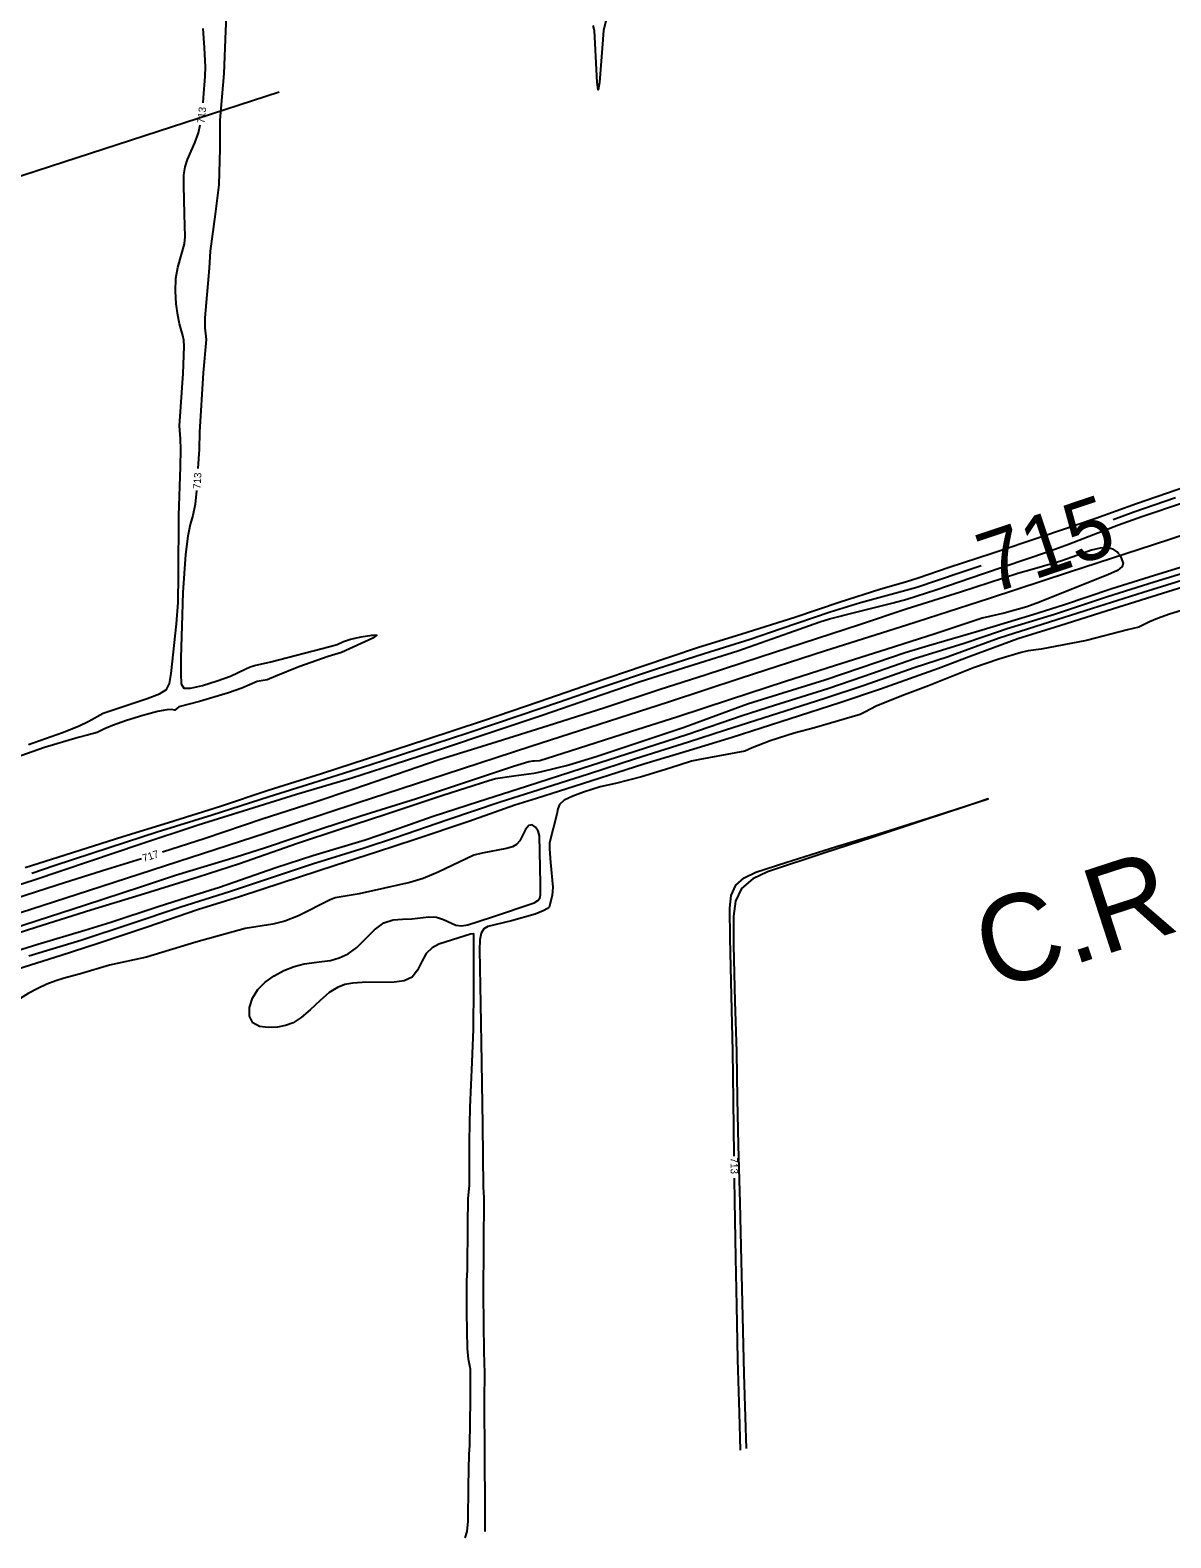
# Model space of a CAD drawing. Extents: x -468548933 to 3387700, y -306089263 to 1207014.
# Drawn here: x 1836234 to 1836853, y 535354 to 536172 of the extents above; entities that cross this region are included whole.
import ezdxf

# ---------------------------------------------------------------- set-up
doc = ezdxf.new("R2010")
doc.units = 0
for name, color, linetype in [('DT_X_Contour_Minor', 7, 'Continuous'), ('Level 14', 7, 'Continuous'), ('Level 19', 7, 'Continuous'), ('Level 40', 7, 'Continuous')]:
    doc.layers.add(name, color=color, linetype=linetype)

msp = doc.modelspace()

# ---------------------------------------------------------------- linework, layer by layer
at = {"layer": 'DT_X_Contour_Minor'}
for points in [[(1836341.23, 536193.74), (1836340.1, 536171.52), (1836339.25, 536148.31), (1836337.09, 536123.13), (1836336.97, 536113.77), (1836337.07, 536107.72), (1836336.39, 536087.89), (1836334.51, 536072.08), (1836331.77, 536051.98), (1836331.22, 536042.83), (1836328.9, 536015.9), (1836328.9, 536010.5), (1836329.58, 536004.08), (1836328.03, 535986.09), (1836325.95, 535953.8), (1836325.72, 535944.58), (1836325.16, 535934.2)], [(1836547.88, 536183.58), (1836545.04, 536171.64), (1836544.29, 536162.04), (1836542.91, 536143.51), (1836542.18, 536139.41), (1836541.6, 536143.49), (1836540.23, 536171.61), (1836539.47, 536174.48)], [(1836327.89, 536132.5), (1836328.18, 536135.23), (1836329.13, 536146.74), (1836329.29, 536152.02), (1836328.72, 536162.23), (1836327.9, 536172.68)], [(1836233.32, 535784.37), (1836251.63, 535790.9), (1836260.31, 535794.36), (1836265.96, 535797.03), (1836273.81, 535801.48), (1836282.37, 535804.33), (1836297.66, 535809.32), (1836304.25, 535811.89), (1836308.04, 535814.24), (1836309.73, 535817.47), (1836310.58, 535823.03), (1836313.55, 535849.89), (1836314.37, 535861.52), (1836314.64, 535876.4), (1836314.76, 535908.67), (1836315.67, 535935.09), (1836315.85, 535944.44), (1836315.69, 535950.3), (1836315.06, 535957.35), (1836317.1, 535985.58), (1836317.74, 536000.21), (1836317.55, 536003.71), (1836317.02, 536006.24), (1836315.19, 536012.55), (1836314.19, 536017.31), (1836313.38, 536023.47), (1836312.97, 536030.39), (1836313.22, 536037.19), (1836314.26, 536043.17), (1836317.82, 536055.94), (1836318.14, 536059.74), (1836317.86, 536072.05), (1836317.41, 536087.59), (1836317.55, 536093.31), (1836318.16, 536097.76), (1836319.4, 536101.75), (1836323.53, 536110.81), (1836325.49, 536116.25), (1836326.42, 536120.59)], [(1836231.46, 535717.64), (1836253.18, 535724.62), (1836284.44, 535734.53), (1836309.13, 535742.21), (1836337.31, 535751.02), (1836363.25, 535759.59), (1836392.07, 535768.74), (1836424.87, 535779.34), (1836448.75, 535787.17), (1836480.08, 535797.54), (1836510.27, 535807.77), (1836538.92, 535817.76), (1836566.58, 535827.14), (1836596.09, 535836.97), (1836620.14, 535844.48), (1836648.76, 535853.54), (1836673.39, 535861.8), (1836694.93, 535868.76), (1836709.42, 535872.89), (1836715.8, 535874.88), (1836732.59, 535880.54), (1836755.76, 535888.24), (1836782.8, 535897.23), (1836812.03, 535907.2), (1836834.12, 535915.13), (1836867.11, 535926.48)], [(1836324.41, 535922.22), (1836323.65, 535914.87), (1836322.37, 535908.67), (1836320.96, 535903.78), (1836319.6, 535897.35), (1836318.45, 535887.51), (1836316.98, 535866.82), (1836316.55, 535854.79), (1836315.92, 535831.41), (1836315.77, 535822.73), (1836315.99, 535817.33), (1836317.44, 535815.01), (1836321.16, 535814.99), (1836327.67, 535816.52), (1836335.51, 535818.91), (1836342.73, 535821.49), (1836351.19, 535825.41), (1836353.54, 535826.57), (1836355.78, 535827.25), (1836364.72, 535829.22), (1836396.69, 535837.58), (1836400.67, 535838.59), (1836404.03, 535840.27), (1836407.86, 535841.51), (1836413.69, 535842.84), (1836419.35, 535843.77), (1836422.07, 535843.67), (1836420, 535842.19), (1836402.92, 535834.38), (1836395.77, 535832.21), (1836379.77, 535826.54), (1836367.39, 535821.57), (1836362.68, 535819.54), (1836357.2, 535818.63), (1836348.88, 535814.94), (1836341.77, 535812.47), (1836326.01, 535807.75), (1836314.83, 535804.95), (1836312.57, 535803.03), (1836310.9, 535803.41), (1836308.3, 535803.28), (1836303.25, 535802.3), (1836295.34, 535800.15), (1836286.38, 535797.38), (1836278.73, 535794.75), (1836274.15, 535792.84), (1836270.56, 535790.88), (1836265.73, 535789.65), (1836260.11, 535788.21), (1836241.96, 535782.81), (1836229.09, 535778.36)], [(1836821.43, 535906.44), (1836832.65, 535910.62), (1836855.33, 535918.43)], [(1836218.85, 535705.35), (1836235.72, 535710.83), (1836266.83, 535721.35), (1836293.64, 535730.32), (1836325.34, 535740.87), (1836352.61, 535749.36), (1836378.61, 535757.42), (1836408.51, 535766.44), (1836425.48, 535771.79), (1836458.31, 535782.49), (1836483.68, 535790.93), (1836512.31, 535800.52), (1836532.19, 535807.37), (1836564.47, 535818.34), (1836585.51, 535825.04), (1836617.88, 535835.25), (1836645.5, 535845), (1836662.42, 535850.95), (1836667.69, 535852.59), (1836682.62, 535856.36), (1836702.11, 535861.19), (1836709.48, 535863.23), (1836725.29, 535868.4), (1836751.11, 535877.19), (1836785.76, 535888.87), (1836797.29, 535893.06), (1836824.35, 535903.54), (1836836.93, 535908.16), (1836859.56, 535915.67)], [(1836824.48, 535887.61), (1836825.17, 535886.94), (1836826.84, 535882.87), (1836826.39, 535880.97), (1836823.83, 535878.86), (1836818.63, 535876.39), (1836793.61, 535866.53), (1836781.46, 535861.63), (1836774.55, 535859.16), (1836762.36, 535855.72), (1836750.48, 535852.92), (1836724.85, 535844.46), (1836698.98, 535836.18), (1836670.39, 535827.17), (1836643.77, 535818.52), (1836613.36, 535808.64), (1836585.32, 535799.5), (1836559.68, 535791.35), (1836526.93, 535780.87), (1836510.57, 535775.63), (1836507.66, 535775.31), (1836506.54, 535775.31), (1836504.61, 535774.96), (1836496.26, 535772.47), (1836468.14, 535763.02), (1836443.6, 535755.03), (1836413.4, 535745.6), (1836392.91, 535738.86), (1836361.76, 535728.4), (1836345.85, 535723.38), (1836312.95, 535713.3), (1836294.54, 535707.29), (1836263.56, 535697.14), (1836238.4, 535689.02), (1836211.75, 535680.39)], [(1836824.48, 535887.61), (1836823.56, 535888.94), (1836821.43, 535890.43), (1836818.33, 535891.08), (1836814.38, 535890.88), (1836809.79, 535889.87), (1836799.17, 535886.11), (1836793.09, 535883.94), (1836778.72, 535879.76), (1836769.76, 535877.14), (1836738.58, 535866.99), (1836709.25, 535857.84), (1836684.45, 535849.49), (1836652.86, 535839.16), (1836630.51, 535831.93), (1836600.2, 535822.03), (1836575.87, 535814.23), (1836545.75, 535804.39), (1836515.08, 535794.54), (1836484.43, 535785.03), (1836455.89, 535776.03), (1836438.62, 535770.21), (1836409.69, 535760.18), (1836388.14, 535753.04), (1836359.94, 535743.9), (1836329.07, 535733.44), (1836305.91, 535726.03)], [(1836866.8, 535883.15), (1836843.94, 535876.16), (1836820.79, 535868.86), (1836794.49, 535860.01), (1836777.83, 535854.74), (1836748.68, 535845.97), (1836721.33, 535837.92), (1836708.67, 535834.17), (1836684.78, 535825.95), (1836665.14, 535819.32), (1836642.26, 535812.26), (1836623.17, 535806.34), (1836612.85, 535802.59), (1836588.82, 535793.68), (1836572.49, 535788.2), (1836541.15, 535777.77), (1836526.27, 535773.25), (1836511.47, 535769.62), (1836507.36, 535768.77), (1836496.43, 535767.24), (1836486.58, 535765.81), (1836482.89, 535764.72), (1836457.9, 535756.77), (1836426.95, 535746.45), (1836402.08, 535738.37), (1836379.05, 535730.66), (1836347.74, 535719.67), (1836325.26, 535712.55), (1836293.83, 535702.81), (1836267.09, 535694.55), (1836237.31, 535685.25), (1836206.63, 535675.48)], [(1836224.01, 535661.65), (1836250.95, 535670.17), (1836270.56, 535676.53), (1836297.53, 535685.61), (1836324.97, 535694.92), (1836347.63, 535702.07), (1836370.82, 535709.65), (1836399.54, 535719.06), (1836422.57, 535726.35), (1836442.41, 535732.9), (1836471.96, 535742.93), (1836496.96, 535751.69), (1836508.73, 535755.41), (1836533.65, 535763.3), (1836566.93, 535773.88), (1836591.63, 535781.34), (1836614.87, 535788.5), (1836646.37, 535798.57), (1836673.3, 535807.3), (1836695.33, 535814.67), (1836726.68, 535825.82), (1836743.38, 535832.09), (1836769.67, 535841.94), (1836792.55, 535849.05), (1836821.67, 535858.17), (1836851.1, 535867.43), (1836879.51, 535876.22)], [(1836868.61, 535876.49), (1836837.71, 535866.93), (1836810.31, 535858.18), (1836783.01, 535849.49), (1836759.6, 535842.03), (1836731.91, 535832.07), (1836713.55, 535825.97), (1836686.49, 535816.48), (1836665.11, 535809.4), (1836639.59, 535801.3), (1836611.29, 535792.12), (1836591.21, 535785.63), (1836562.45, 535776.59), (1836536.94, 535768.37), (1836506.18, 535758.64), (1836489, 535753.09), (1836460.66, 535743.52), (1836432.32, 535733.8), (1836415.27, 535728.17), (1836387.18, 535719.53), (1836361.26, 535710.93), (1836342.26, 535704.47), (1836315.93, 535696.18), (1836288.36, 535686.96), (1836261.55, 535678.22), (1836233.47, 535669.55)], [(1836235.01, 535714.72), (1836247.23, 535718.83), (1836277.61, 535728.68), (1836302.98, 535737.04), (1836332.88, 535746.37), (1836363.82, 535756.24), (1836387.46, 535763.6), (1836418.44, 535773.38), (1836444.97, 535782.02), (1836471.41, 535790.76), (1836499.82, 535800.28), (1836520.63, 535807.47), (1836543.71, 535815.35), (1836573.84, 535825.52), (1836599.63, 535833.79), (1836624.54, 535841.59), (1836641.46, 535847.26), (1836667.9, 535856.38), (1836684.39, 535861.49), (1836714.9, 535869.74), (1836737.95, 535877.55), (1836749.8, 535881.53)], [(1836869.77, 535880.51), (1836843.74, 535872.45), (1836818.47, 535864.47), (1836789.69, 535854.99), (1836763.93, 535847.09)], [(1836877.95, 535863.09), (1836851.99, 535855.09)], [(1836851.99, 535855.09), (1836845.45, 535852.82), (1836841.19, 535850.98), (1836835.42, 535848.1), (1836829.21, 535846.65), (1836807.05, 535840.79), (1836782.4, 535836.22), (1836775.45, 535835.22), (1836771.59, 535834.38), (1836759.44, 535830.76), (1836745.63, 535826.04), (1836721.25, 535816.34), (1836706.87, 535810.91), (1836692.91, 535805.16), (1836686.8, 535801.93), (1836684.3, 535800.62), (1836659.44, 535793.54), (1836648.39, 535790.66), (1836635.47, 535786.39), (1836625.72, 535782.68), (1836621.69, 535780.85), (1836597.22, 535776.26), (1836592.87, 535775.35), (1836581, 535771.53), (1836565.69, 535766.87), (1836551.6, 535763.35), (1836543.18, 535761.51), (1836534.3, 535758.59), (1836528.52, 535756.45), (1836523.72, 535754.16), (1836521.19, 535751.97), (1836520.26, 535749.59), (1836519.76, 535746.64), (1836515.81, 535731.16), (1836515.72, 535727.9), (1836516.31, 535720.49), (1836517.62, 535706.98), (1836517.2, 535702.54), (1836515.62, 535696.23), (1836514.75, 535695.5), (1836512.34, 535694.14), (1836507.93, 535692.49), (1836495.23, 535688.85), (1836482.31, 535685.72), (1836480.16, 535684.43), (1836478.72, 535682.2), (1836478, 535678.56), (1836477.82, 535672.99), (1836478.33, 535643.72), (1836478.9, 535611.9), (1836479.4, 535578.12), (1836479.85, 535544.59), (1836480.1, 535538.57), (1836480.05, 535512.97), (1836479.78, 535486.18), (1836480.2, 535455.12), (1836480.53, 535443.42), (1836480.41, 535429.07), (1836480.58, 535397.51), (1836480.8, 535372.08), (1836480.65, 535357.53)], [(1836763.93, 535847.09), (1836752.33, 535843.25), (1836740.64, 535839.24), (1836713.69, 535830.84), (1836686.2, 535821.26), (1836666.81, 535814.71), (1836637.79, 535805.63), (1836620.26, 535799.93), (1836590.79, 535789.93), (1836562.22, 535780.63), (1836533.58, 535771.33), (1836503.23, 535761.72), (1836477.25, 535753.3), (1836452.75, 535745.3), (1836430.64, 535737.55), (1836415.75, 535732.47), (1836387.4, 535724.09), (1836367.41, 535717.5), (1836336.9, 535706.86), (1836323.41, 535702.66), (1836303.5, 535696.4), (1836277.84, 535687.94), (1836263.74, 535683.62), (1836238.3, 535675.98), (1836208.71, 535666.66)], [(1836615.92, 535561.2), (1836615.92, 535561.44), (1836615.6, 535591.36), (1836615.27, 535618.2), (1836614.48, 535648.13), (1836613.77, 535679.32), (1836613.6, 535695.66), (1836614.38, 535702.58), (1836616.75, 535708.15), (1836621.28, 535712.19), (1836627.67, 535715.18), (1836643.92, 535720.48), (1836671.49, 535729.11), (1836693.7, 535735.87), (1836725.14, 535745.67), (1836753.64, 535754.91), (1836741.05, 535750.72), (1836719.02, 535743.39), (1836690.77, 535734.05), (1836665.17, 535725.66), (1836633.92, 535715.38), (1836625.98, 535711.63), (1836619.86, 535706.42), (1836616.59, 535699.45), (1836615.48, 535691.38), (1836615.59, 535675.43), (1836616.33, 535645.28), (1836617.11, 535617.67), (1836617.55, 535592.35), (1836618.12, 535567.08), (1836619.01, 535535.85), (1836619.69, 535504.43), (1836620.39, 535474.18), (1836621.21, 535443.16), (1836621.93, 535419.62), (1836622.35, 535402.68)], [(1836470.08, 535354.16), (1836471.17, 535357.52), (1836471.64, 535363.18), (1836471.84, 535382.45), (1836472.13, 535399.48), (1836472.59, 535404.27), (1836473.01, 535429.03), (1836472.94, 535445.72), (1836471.78, 535451.14), (1836471.35, 535456.82), (1836470.87, 535476.31), (1836470.92, 535493.81), (1836471.24, 535499.32), (1836471.41, 535523.92), (1836471.74, 535538.15), (1836472.33, 535545.34), (1836472.49, 535569.49), (1836472.69, 535587.56), (1836473.86, 535612.07), (1836474.64, 535630), (1836474.8, 535652.83), (1836474.83, 535681.5), (1836474.46, 535681.82), (1836472.93, 535681.58), (1836459.69, 535677.4), (1836455.82, 535676.08), (1836452.11, 535674.17), (1836448.96, 535671.15), (1836446.56, 535666.81), (1836444.28, 535662.09), (1836441.26, 535658.24), (1836436.9, 535656.17), (1836431.5, 535655.48), (1836414.19, 535655.39), (1836409.18, 535655.04), (1836404.83, 535654.29), (1836400.74, 535652.73), (1836396.36, 535649.88), (1836391.36, 535645.54), (1836386.08, 535640.62), (1836381.08, 535636.3), (1836376.71, 535633.48), (1836372.62, 535631.95), (1836368.25, 535631.21), (1836363.3, 535630.94), (1836358.5, 535631.5), (1836354.83, 535633.43), (1836353.07, 535637.06), (1836353.14, 535641.8), (1836354.76, 535646.84), (1836357.67, 535651.48), (1836361.62, 535655.57), (1836366.4, 535659.05), (1836371.75, 535661.89), (1836377.33, 535664.03), (1836382.73, 535665.46), (1836392.33, 535666.67), (1836396.94, 535667.34), (1836401.69, 535668.67), (1836406.54, 535670.94), (1836411.39, 535674.41), (1836420.95, 535683.92), (1836425.87, 535687.66), (1836430.98, 535689.38), (1836436.15, 535689.76), (1836441.2, 535689.84), (1836450.43, 535690.94), (1836454.53, 535690.83), (1836458.27, 535689.59), (1836464.96, 535686.42), (1836468.1, 535686.06), (1836471.41, 535686.6), (1836484.41, 535690.76), (1836507.52, 535698.55), (1836509.54, 535699.78), (1836510.53, 535701.01), (1836510.91, 535702.93), (1836510.96, 535709), (1836510.45, 535734.97), (1836509.62, 535737.47), (1836508.2, 535739.59), (1836506.39, 535740.83), (1836504.51, 535740.55), (1836502.8, 535738.41), (1836499.64, 535732.23), (1836497.92, 535730.17), (1836495.65, 535728.91), (1836492.4, 535727.99), (1836479.27, 535725.44), (1836474.68, 535724.44), (1836455.43, 535715.19), (1836447.27, 535711.84), (1836440.13, 535709.63), (1836412.49, 535703.45), (1836399.64, 535701.19), (1836396.84, 535700.18), (1836379.58, 535691.59), (1836372.2, 535688.61), (1836365.75, 535686.94), (1836350.69, 535684.65), (1836324.06, 535677.28)], [(1836294.45, 535722.46), (1836273.31, 535715.89), (1836248.87, 535708.13), (1836220.18, 535698.89), (1836195.43, 535690.88), (1836165.66, 535681.14), (1836141.69, 535673), (1836118.09, 535665.4), (1836086.48, 535655.28), (1836061.91, 535647.37), (1836030.43, 535636.9), (1836000.56, 535627.06), (1835969.72, 535617.51), (1835943.6, 535609.33), (1835915.91, 535600.68), (1835897.39, 535594.8), (1835868.42, 535585.93), (1835844.96, 535578.58), (1835822.72, 535571.41), (1835800.33, 535563.36), (1835783.83, 535557.66), (1835773.89, 535554.55)], [(1836324.06, 535677.28), (1836297.22, 535669.03), (1836277.24, 535664.71), (1836261.44, 535660.01), (1836252.53, 535657.69), (1836247.99, 535656.27), (1836243.25, 535654.48), (1836238.3, 535652.18), (1836233.13, 535649.32), (1836210.57, 535635.46), (1836205.7, 535632.78), (1836201.87, 535631.01), (1836198.39, 535629.96), (1836194.34, 535629.29), (1836165.31, 535625.92), (1836152.91, 535624.37), (1836148.61, 535623.6), (1836134.16, 535618.23), (1836121.69, 535614.64)], [(1836619.38, 535401.71), (1836618.81, 535422.04), (1836617.95, 535450.81), (1836617.33, 535480.05), (1836616.82, 535506.07), (1836616.22, 535536.99), (1836616.07, 535549.2)]]:
    msp.add_lwpolyline(points, dxfattribs=at)
at = {"layer": 'Level 14'}
msp.add_lwpolyline([(1836891.43, 535908.38), (1836843.39, 535892.69), (1836797.82, 535877.82), (1836754.36, 535863.66), (1836709.62, 535849.19), (1836665.53, 535835.18), (1836619.79, 535820.33), (1836580.24, 535807.46), (1836505.75, 535783.43), (1836459.21, 535768.23), (1836411.52, 535752.69), (1836362.16, 535736.38), (1836314.21, 535720.72), (1836265.72, 535705.02), (1836216.47, 535689.08)], dxfattribs=at)
at = {"layer": 'Level 40'}
msp.add_line((1835593.63, 535886.58), (1836369.22, 536138.38), dxfattribs=at)

# ---------------------------------------------------------------- texts
at = {"layer": 'Level 19'}
for s, height, rotation, p in [('713', 4, 83.89821, (1836328.68, 536121.13)), ('713', 4, 86.92916, (1836326.55, 535922.88)), ('715', 33, 18.54664, (1836755.02, 535865.87)), ('717', 4, 17.26322, (1836295.75, 535720.77)), ('713', 4, 270.69391, (1836613.93, 535560.4))]:
    msp.add_text(s, height=height, rotation=rotation, dxfattribs=at).set_placement(p)
at = {"layer": 'Level 40'}
msp.add_text('C.R. 8', height=46.8, rotation=17.99893, dxfattribs=at).set_placement((1836756.07, 535650.53))

doc.saveas('drawing.dxf')
